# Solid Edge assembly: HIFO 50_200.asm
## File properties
Title: Zylinder
Author: ahadarics
Template: iso assembly.asm
Last saved by: ahadarics
Revision: 30
Application: Solid Edge
Username: ahadarics
Dokumentum tartalom típus: 1
Document Number: HIFO 50/200
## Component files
Profilrohr 50_200.par
Mutter.par
Kolbenstange 50_200.par
Kit_1.par
Kit_2.par
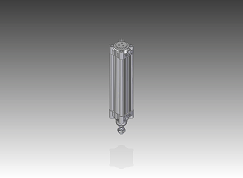
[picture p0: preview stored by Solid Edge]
